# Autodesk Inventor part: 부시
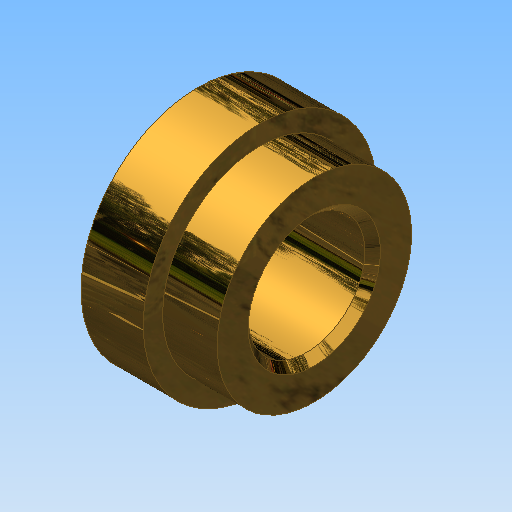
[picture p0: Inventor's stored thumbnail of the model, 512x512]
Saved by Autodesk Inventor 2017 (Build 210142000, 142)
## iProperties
Created: 2011-04
Part Number: 부시
Document SubType Name: Modeling
Density: 1 g/cm^3
Material: 일반
Appearance: 황동 - 새틴
Author: pww
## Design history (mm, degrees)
sketch "스케치1"
  geometry: L1 (0, 0)-(15, 0); L2 (0, 7.5)-(15, 7.5); L3 (15, 7.5)-(15, 12.5); L4 (15, 12.5)-(8, 12.5); L5 (8, 12.5)-(8, 15); L6 (8, 15)-(0, 15); L7 (0, 15)-(0, 7.5)
  constraints: 14 end point, 4 parallel, 2 vertical alignment, 1 horizontal, 1 perpendicular, 1 vertical
  dimensions: "d0" = 15 distance of L1.start L1.end; "d1" = 15 diameter of L2 L1; "d2" = 25 diameter of L4 L1; "d3" = 8 distance of L5.end L6.end; "d4" = 30 diameter of L6 L1
revolve "회전1" sketch "스케치1" stored, may be unused: angle "d5" = 90 deg
chamfer "모따기1" distance "d6" = 1; stored, may be unused: second distance "d7" = 2, angle "d8" = 45 deg
node "솔리드1"
